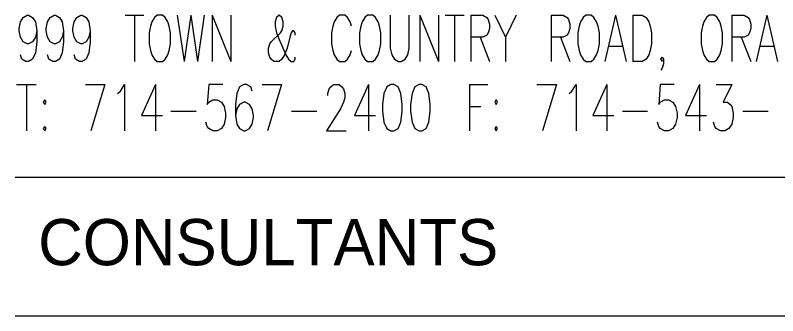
# Model space of a CAD drawing. Extents: x 0 to 3.5, y -0.08 to 2.5.
# Drawn here: x 3.1667 to 3.3385, y 1.6102 to 1.678 of the extents above; entities that cross this region are included whole.
import ezdxf

# ---------------------------------------------------------------- set-up
doc = ezdxf.new("R2010")
doc.units = 0
doc.layers.add('G-ANNO-TTLB', color=7, linetype='Continuous')

msp = doc.modelspace()

# ---------------------------------------------------------------- linework, layer by layer
at = {"layer": 'G-ANNO-TTLB'}
msp.add_line((3.16667, 1.61025), (3.45833, 1.61025), dxfattribs=at)
for points in [[(3.1715, 1.67448), (3.1712, 1.67299), (3.17059, 1.672), (3.16969, 1.67151), (3.16938, 1.67151), (3.16848, 1.672), (3.16787, 1.67299), (3.16757, 1.67448), (3.16757, 1.67498), (3.16787, 1.67647), (3.16848, 1.67746), (3.16938, 1.67795), (3.16969, 1.67795), (3.17059, 1.67746), (3.1712, 1.67647), (3.1715, 1.67448), (3.1715, 1.672), (3.1712, 1.66952), (3.17059, 1.66803), (3.16969, 1.66754), (3.16908, 1.66754), (3.16818, 1.66803), (3.16787, 1.66903)], [(3.17754, 1.67448), (3.17723, 1.67299), (3.17663, 1.672), (3.17573, 1.67151), (3.17542, 1.67151), (3.17452, 1.672), (3.17391, 1.67299), (3.17361, 1.67448), (3.17361, 1.67498), (3.17391, 1.67647), (3.17452, 1.67746), (3.17542, 1.67795), (3.17573, 1.67795), (3.17663, 1.67746), (3.17723, 1.67647), (3.17754, 1.67448), (3.17754, 1.672), (3.17723, 1.66952), (3.17663, 1.66803), (3.17573, 1.66754), (3.17512, 1.66754), (3.17422, 1.66803), (3.17391, 1.66903)], [(3.18358, 1.67448), (3.18327, 1.67299), (3.18267, 1.672), (3.18176, 1.67151), (3.18146, 1.67151), (3.18056, 1.672), (3.17995, 1.67299), (3.17965, 1.67448), (3.17965, 1.67498), (3.17995, 1.67647), (3.18056, 1.67746), (3.18146, 1.67795), (3.18176, 1.67795), (3.18267, 1.67746), (3.18327, 1.67647), (3.18358, 1.67448), (3.18358, 1.672), (3.18327, 1.66952), (3.18267, 1.66803), (3.18176, 1.66754), (3.18116, 1.66754), (3.18025, 1.66803), (3.17995, 1.66903)], [(3.19143, 1.67795), (3.19565, 1.67795)], [(3.19354, 1.67795), (3.19354, 1.66754)], [(3.19867, 1.67795), (3.19807, 1.67746), (3.19747, 1.67647), (3.19716, 1.67547), (3.19686, 1.67399), (3.19686, 1.67151), (3.19716, 1.67002), (3.19747, 1.66903), (3.19807, 1.66803), (3.19867, 1.66754), (3.19988, 1.66754), (3.20049, 1.66803), (3.20109, 1.66903), (3.20139, 1.67002), (3.20169, 1.67151), (3.20169, 1.67399), (3.20139, 1.67547), (3.20109, 1.67647), (3.20049, 1.67746), (3.19988, 1.67795), (3.19867, 1.67795)], [(3.2032, 1.67795), (3.20471, 1.66754)], [(3.20622, 1.67795), (3.20471, 1.66754)], [(3.20622, 1.67795), (3.20773, 1.66754)], [(3.20924, 1.67795), (3.20773, 1.66754)], [(3.21105, 1.67795), (3.21105, 1.66754)], [(3.21105, 1.67795), (3.21528, 1.66754)], [(3.21528, 1.67795), (3.21528, 1.66754)], [(3.22977, 1.67349), (3.22977, 1.67399), (3.22947, 1.67448), (3.22917, 1.67448), (3.22887, 1.67399), (3.22857, 1.67299), (3.22796, 1.67051), (3.22736, 1.66903), (3.22676, 1.66803), (3.22615, 1.66754), (3.22494, 1.66754), (3.22434, 1.66803), (3.22404, 1.66853), (3.22374, 1.66952), (3.22374, 1.67051), (3.22404, 1.67151), (3.22434, 1.672), (3.22645, 1.67399), (3.22676, 1.67448), (3.22706, 1.67547), (3.22706, 1.67647), (3.22676, 1.67746), (3.22615, 1.67795), (3.22555, 1.67746), (3.22525, 1.67647), (3.22525, 1.67547), (3.22555, 1.67399), (3.22615, 1.6725), (3.22766, 1.66903), (3.22826, 1.66803), (3.22887, 1.66754), (3.22947, 1.66754), (3.22977, 1.66803), (3.22977, 1.66853)], [(3.24246, 1.67547), (3.24215, 1.67647), (3.24155, 1.67746), (3.24095, 1.67795), (3.23974, 1.67795), (3.23914, 1.67746), (3.23853, 1.67647), (3.23823, 1.67547), (3.23793, 1.67399), (3.23793, 1.67151), (3.23823, 1.67002), (3.23853, 1.66903), (3.23914, 1.66803), (3.23974, 1.66754), (3.24095, 1.66754), (3.24155, 1.66803), (3.24215, 1.66903), (3.24246, 1.67002)], [(3.24608, 1.67795), (3.24548, 1.67746), (3.24487, 1.67647), (3.24457, 1.67547), (3.24427, 1.67399), (3.24427, 1.67151), (3.24457, 1.67002), (3.24487, 1.66903), (3.24548, 1.66803), (3.24608, 1.66754), (3.24729, 1.66754), (3.24789, 1.66803), (3.2485, 1.66903), (3.2488, 1.67002), (3.2491, 1.67151), (3.2491, 1.67399), (3.2488, 1.67547), (3.2485, 1.67647), (3.24789, 1.67746), (3.24729, 1.67795), (3.24608, 1.67795)], [(3.25121, 1.67795), (3.25121, 1.67051), (3.25152, 1.66903), (3.25212, 1.66803), (3.25302, 1.66754), (3.25363, 1.66754), (3.25453, 1.66803), (3.25514, 1.66903), (3.25544, 1.67051), (3.25544, 1.67795)], [(3.25786, 1.67795), (3.25786, 1.66754)], [(3.25786, 1.67795), (3.26208, 1.66754)], [(3.26208, 1.67795), (3.26208, 1.66754)], [(3.26359, 1.67795), (3.26782, 1.67795)], [(3.26571, 1.67795), (3.26571, 1.66754)], [(3.26933, 1.67795), (3.26933, 1.66754)], [(3.26933, 1.67795), (3.27205, 1.67795), (3.27295, 1.67746), (3.27326, 1.67696), (3.27356, 1.67597), (3.27356, 1.67498), (3.27326, 1.67399), (3.27295, 1.67349), (3.27205, 1.67299), (3.26933, 1.67299)], [(3.27477, 1.67795), (3.27718, 1.67299), (3.27718, 1.66754)], [(3.2796, 1.67795), (3.27718, 1.67299)], [(3.28745, 1.67795), (3.28745, 1.66754)], [(3.28745, 1.67795), (3.29017, 1.67795), (3.29107, 1.67746), (3.29137, 1.67696), (3.29167, 1.67597), (3.29167, 1.67498), (3.29137, 1.67399), (3.29107, 1.67349), (3.29017, 1.67299), (3.28745, 1.67299)], [(3.2953, 1.67795), (3.29469, 1.67746), (3.29409, 1.67647), (3.29379, 1.67547), (3.29349, 1.67399), (3.29349, 1.67151), (3.29379, 1.67002), (3.29409, 1.66903), (3.29469, 1.66803), (3.2953, 1.66754), (3.29651, 1.66754), (3.29711, 1.66803), (3.29771, 1.66903), (3.29802, 1.67002), (3.29832, 1.67151), (3.29832, 1.67399), (3.29802, 1.67547), (3.29771, 1.67647), (3.29711, 1.67746), (3.29651, 1.67795), (3.2953, 1.67795)], [(3.30194, 1.67795), (3.29953, 1.66754)], [(3.30194, 1.67795), (3.30436, 1.66754)], [(3.30587, 1.67795), (3.30587, 1.66754)], [(3.30587, 1.67795), (3.30798, 1.67795), (3.30889, 1.67746), (3.30949, 1.67647), (3.30979, 1.67547), (3.31009, 1.67399), (3.31009, 1.67151), (3.30979, 1.67002), (3.30949, 1.66903), (3.30889, 1.66803), (3.30798, 1.66754), (3.30587, 1.66754)], [(3.32308, 1.67795), (3.32247, 1.67746), (3.32187, 1.67647), (3.32157, 1.67547), (3.32127, 1.67399), (3.32127, 1.67151), (3.32157, 1.67002), (3.32187, 1.66903), (3.32247, 1.66803), (3.32308, 1.66754), (3.32429, 1.66754), (3.32489, 1.66803), (3.32549, 1.66903), (3.3258, 1.67002), (3.3261, 1.67151), (3.3261, 1.67399), (3.3258, 1.67547), (3.32549, 1.67647), (3.32489, 1.67746), (3.32429, 1.67795), (3.32308, 1.67795)], [(3.32821, 1.67795), (3.32821, 1.66754)], [(3.32821, 1.67795), (3.33093, 1.67795), (3.33183, 1.67746), (3.33214, 1.67696), (3.33244, 1.67597), (3.33244, 1.67498), (3.33214, 1.67399), (3.33183, 1.67349), (3.33093, 1.67299), (3.32821, 1.67299)], [(3.33606, 1.67795), (3.33365, 1.66754)], [(3.33606, 1.67795), (3.33848, 1.66754)], [(3.27144, 1.67299), (3.27356, 1.66754)], [(3.28956, 1.67299), (3.29167, 1.66754)], [(3.33032, 1.67299), (3.33244, 1.66754)], [(3.30043, 1.67101), (3.30345, 1.67101)], [(3.33455, 1.67101), (3.33757, 1.67101)], [(3.31281, 1.66803), (3.31251, 1.66754), (3.31221, 1.66803), (3.31251, 1.66853), (3.31281, 1.66803), (3.31281, 1.66704), (3.31251, 1.66605), (3.31221, 1.66555)], [(3.16698, 1.66233), (3.17141, 1.66233)], [(3.16919, 1.66233), (3.16919, 1.65191)], [(3.18247, 1.66233), (3.18689, 1.66233)], [(3.18689, 1.66233), (3.18373, 1.65191)], [(3.18974, 1.66034), (3.19037, 1.66084), (3.19132, 1.66233), (3.19132, 1.65191)], [(3.19827, 1.66233), (3.19511, 1.65538), (3.19985, 1.65538)], [(3.19827, 1.66233), (3.19827, 1.65191)], [(3.21344, 1.66233), (3.21028, 1.66233), (3.20996, 1.65786), (3.21028, 1.65836), (3.21123, 1.65886), (3.21218, 1.65886), (3.21312, 1.65836), (3.21376, 1.65737), (3.21407, 1.65588), (3.21407, 1.65489), (3.21376, 1.6534), (3.21312, 1.65241), (3.21218, 1.65191), (3.21123, 1.65191), (3.21028, 1.65241), (3.20996, 1.6529), (3.20965, 1.6539)], [(3.22008, 1.66084), (3.21976, 1.66183), (3.21881, 1.66233), (3.21818, 1.66233), (3.21723, 1.66183), (3.2166, 1.66034), (3.21628, 1.65786), (3.21628, 1.65538), (3.2166, 1.6534), (3.21723, 1.65241), (3.21818, 1.65191), (3.2185, 1.65191), (3.21944, 1.65241), (3.22008, 1.6534), (3.22039, 1.65489), (3.22039, 1.65538), (3.22008, 1.65687), (3.21944, 1.65786), (3.2185, 1.65836), (3.21818, 1.65836), (3.21723, 1.65786), (3.2166, 1.65687), (3.21628, 1.65538)], [(3.22229, 1.66233), (3.22671, 1.66233)], [(3.22671, 1.66233), (3.22355, 1.65191)], [(3.23714, 1.65985), (3.23714, 1.66034), (3.23746, 1.66134), (3.23777, 1.66183), (3.23841, 1.66233), (3.23967, 1.66233), (3.2403, 1.66183), (3.24062, 1.66134), (3.24093, 1.66034), (3.24093, 1.65935), (3.24062, 1.65836), (3.23999, 1.65687), (3.23683, 1.65191), (3.24125, 1.65191)], [(3.24631, 1.66233), (3.24315, 1.65538), (3.24789, 1.65538)], [(3.24631, 1.66233), (3.24631, 1.65191)], [(3.25136, 1.66233), (3.25042, 1.66183), (3.24978, 1.66034), (3.24947, 1.65786), (3.24947, 1.65638), (3.24978, 1.6539), (3.25042, 1.65241), (3.25136, 1.65191), (3.252, 1.65191), (3.25294, 1.65241), (3.25358, 1.6539), (3.25389, 1.65638), (3.25389, 1.65786), (3.25358, 1.66034), (3.25294, 1.66183), (3.252, 1.66233), (3.25136, 1.66233)], [(3.25768, 1.66233), (3.25674, 1.66183), (3.2561, 1.66034), (3.25579, 1.65786), (3.25579, 1.65638), (3.2561, 1.6539), (3.25674, 1.65241), (3.25768, 1.65191), (3.25832, 1.65191), (3.25926, 1.65241), (3.2599, 1.6539), (3.26021, 1.65638), (3.26021, 1.65786), (3.2599, 1.66034), (3.25926, 1.66183), (3.25832, 1.66233), (3.25768, 1.66233)], [(3.26906, 1.66233), (3.26906, 1.65191)], [(3.26906, 1.66233), (3.27317, 1.66233)], [(3.28423, 1.66233), (3.28866, 1.66233)], [(3.28866, 1.66233), (3.2855, 1.65191)], [(3.2915, 1.66034), (3.29213, 1.66084), (3.29308, 1.66233), (3.29308, 1.65191)], [(3.30003, 1.66233), (3.29687, 1.65538), (3.30161, 1.65538)], [(3.30003, 1.66233), (3.30003, 1.65191)], [(3.3152, 1.66233), (3.31204, 1.66233), (3.31173, 1.65786), (3.31204, 1.65836), (3.31299, 1.65886), (3.31394, 1.65886), (3.31489, 1.65836), (3.31552, 1.65737), (3.31583, 1.65588), (3.31583, 1.65489), (3.31552, 1.6534), (3.31489, 1.65241), (3.31394, 1.65191), (3.31299, 1.65191), (3.31204, 1.65241), (3.31173, 1.6529), (3.31141, 1.6539)], [(3.32089, 1.66233), (3.31773, 1.65538), (3.32247, 1.65538)], [(3.32089, 1.66233), (3.32089, 1.65191)], [(3.32468, 1.66233), (3.32816, 1.66233), (3.32626, 1.65836), (3.32721, 1.65836), (3.32784, 1.65786), (3.32816, 1.65737), (3.32848, 1.65588), (3.32848, 1.65489), (3.32816, 1.6534), (3.32753, 1.65241), (3.32658, 1.65191), (3.32563, 1.65191), (3.32468, 1.65241), (3.32437, 1.6529), (3.32405, 1.6539)], [(3.1733, 1.65886), (3.17299, 1.65836), (3.1733, 1.65786), (3.17362, 1.65836), (3.1733, 1.65886)], [(3.27507, 1.65886), (3.27475, 1.65836), (3.27507, 1.65786), (3.27538, 1.65836), (3.27507, 1.65886)], [(3.26906, 1.65737), (3.27159, 1.65737)], [(3.20175, 1.65638), (3.20744, 1.65638)], [(3.22893, 1.65638), (3.23461, 1.65638)], [(3.30351, 1.65638), (3.3092, 1.65638)], [(3.33069, 1.65638), (3.33638, 1.65638)], [(3.1733, 1.6529), (3.17299, 1.65241), (3.1733, 1.65191), (3.17362, 1.65241), (3.1733, 1.6529)], [(3.27507, 1.6529), (3.27475, 1.65241), (3.27507, 1.65191), (3.27538, 1.65241), (3.27507, 1.6529)], [(3.16667, 1.6415), (3.45833, 1.6415)]]:
    msp.add_lwpolyline(points, dxfattribs=at)

# ---------------------------------------------------------------- texts
msp.add_text('CONSULTANTS', height=0.0104167, dxfattribs=at).set_placement((3.17183, 1.62162))

doc.saveas('drawing.dxf')
